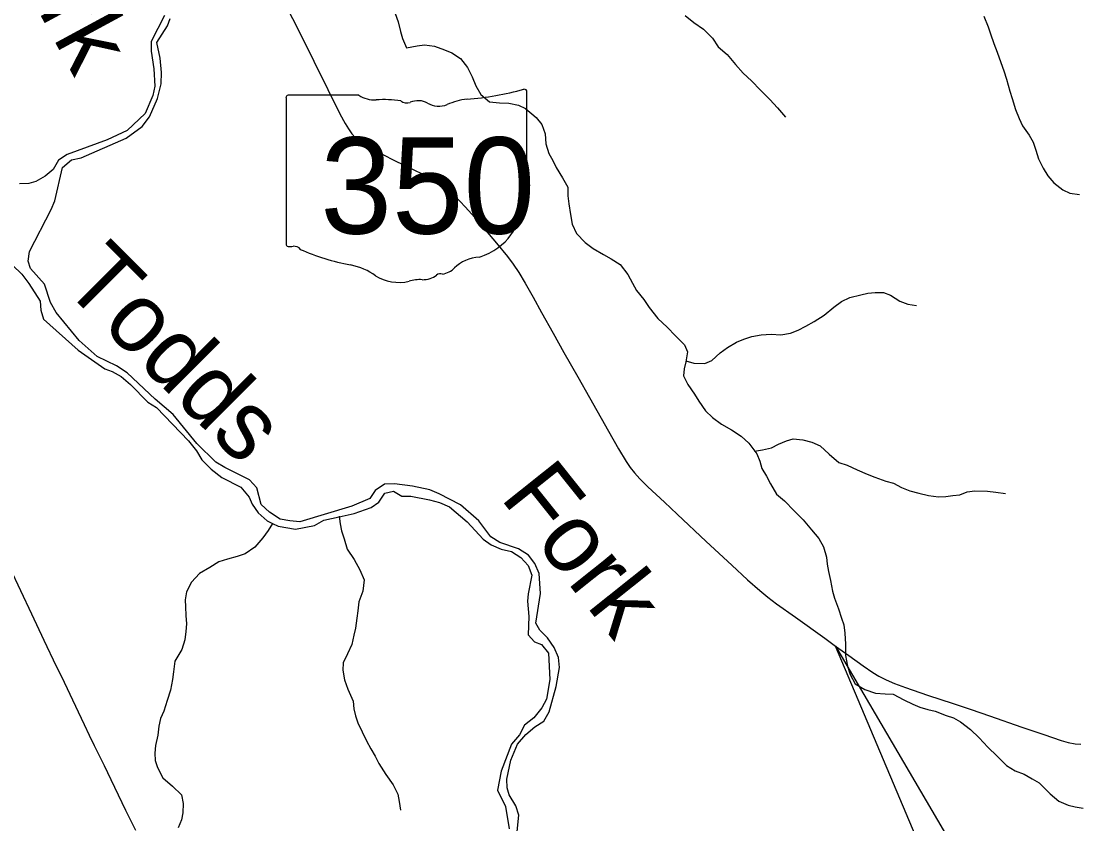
# Model space of a CAD drawing. Extents: x 0 to 34, y 0 to 22.
# Drawn here: x 18.692 to 20.137, y 17.343 to 18.443 of the extents above; entities that cross this region are included whole.
import ezdxf

# ---------------------------------------------------------------- set-up
doc = ezdxf.new("R2010")
doc.units = 0
for name, color, linetype in [('GM_X_County_Road', 7, 'Continuous'), ('GM_X_Major_River', 7, 'Continuous'), ('GM_X_Major_River_Text', 7, 'Continuous'), ('GM_X_Minor_River', 7, 'Continuous'), ('GM_X_State_Location', 7, 'Continuous'), ('GM_X_State_Route', 7, 'Continuous'), ('GM_X_State_Shield', 7, 'Continuous'), ('SH_Text', 7, 'Continuous')]:
    doc.layers.add(name, color=color, linetype=linetype)

msp = doc.modelspace()

# ---------------------------------------------------------------- linework, layer by layer
at = {"layer": 'GM_X_County_Road'}
msp.add_lwpolyline([(18.8488, 17.3345), (18.8352, 17.3618), (18.8252, 17.3825), (18.8151, 17.4038), (18.8059, 17.4227), (18.7996, 17.4354), (18.7922, 17.4504), (18.7855, 17.4644), (18.7784, 17.4788), (18.7701, 17.4962), (18.7474, 17.5445), (18.7402, 17.559), (18.7235, 17.5943), (18.7065, 17.6303), (18.6765, 17.6945)], dxfattribs=at)
at = {"layer": 'GM_X_Major_River'}
for points in [[(18.888, 18.4505), (18.8695, 18.4145), (18.8696, 18.4016), (18.8733, 18.3772), (18.8747, 18.3536), (18.8721, 18.3408), (18.8614, 18.316), (18.8367, 18.2929), (18.8095, 18.2802), (18.7549, 18.26), (18.743, 18.2523), (18.7354, 18.2396), (18.7248, 18.2303), (18.7117, 18.2229), (18.7022, 18.2201), (18.6897, 18.2196)], [(19.3705, 17.3328), (19.3728, 17.3551), (19.3689, 17.3681), (19.3597, 17.383), (19.3569, 17.3926), (19.3564, 17.4047), (19.3622, 17.4308), (19.371, 17.4523), (19.3827, 17.4657), (19.395, 17.4761), (19.4073, 17.4838), (19.4144, 17.4969), (19.4242, 17.5313), (19.4285, 17.5577), (19.4273, 17.5714), (19.4215, 17.5848), (19.4123, 17.5979), (19.4019, 17.6087), (19.396, 17.6183), (19.4025, 17.6588), (19.4008, 17.6861), (19.395, 17.6999), (19.3862, 17.7115), (19.3727, 17.7201), (19.3471, 17.7285), (19.3344, 17.7364), (19.3182, 17.7583), (19.2933, 17.7801), (19.264, 17.7954), (19.2513, 17.8006), (19.2275, 17.8057), (19.2026, 17.8088), (19.1893, 17.8087), (19.1762, 17.7998), (19.1688, 17.789), (19.1443, 17.7785), (19.0731, 17.7571), (19.0594, 17.7581), (19.0462, 17.7607), (19.0317, 17.7701), (19.0201, 17.7805), (19.0145, 17.8034), (19.0042, 17.8146), (18.9704, 17.8312), (18.9584, 17.8387), (18.9321, 17.8642), (18.8999, 17.9039), (18.875, 17.9249), (18.8367, 17.961), (18.8225, 17.9704), (18.7958, 17.9834), (18.7713, 18.0051), (18.7399, 18.0437), (18.7318, 18.0571), (18.7236, 18.0823), (18.7044, 18.104), (18.7012, 18.1139), (18.703, 18.1271), (18.7329, 18.1846), (18.7377, 18.1963), (18.7485, 18.2423), (18.7608, 18.2527), (18.7738, 18.2555), (18.8357, 18.2823), (18.8576, 18.2982), (18.8674, 18.3117), (18.8785, 18.3365), (18.8835, 18.3569), (18.8838, 18.3721), (18.8819, 18.3918), (18.8774, 18.4132), (18.8923, 18.436), (18.8959, 18.4462)], [(18.6668, 18.1214), (18.6925, 18.0959), (18.7024, 18.0835), (18.7179, 18.0593), (18.7187, 18.0468), (18.7223, 18.0346), (18.7699, 17.9919), (18.8061, 17.9665), (18.8163, 17.9629), (18.8286, 17.9558), (18.8413, 17.9449), (18.865, 17.9206), (18.877, 17.9135), (18.9208, 17.8679), (18.9319, 17.8544), (18.9392, 17.8417), (18.9518, 17.8289), (18.9663, 17.8176), (18.9926, 17.8046), (19.0037, 17.7907), (19.008, 17.7812), (19.0161, 17.7692), (19.0284, 17.7584), (19.0356, 17.7547), (19.0434, 17.7509), (19.0672, 17.747), (19.0934, 17.7518), (19.1061, 17.7591), (19.127, 17.7639), (19.1476, 17.7685), (19.1708, 17.7764), (19.1812, 17.7838), (19.1894, 17.7962), (19.2016, 17.799), (19.2128, 17.7923), (19.2249, 17.792), (19.2506, 17.787), (19.2645, 17.7833), (19.2781, 17.7777), (19.3023, 17.7571), (19.3241, 17.7332), (19.335, 17.7254), (19.3488, 17.7194), (19.3628, 17.7165), (19.3755, 17.7079), (19.3855, 17.6971), (19.3906, 17.6841), (19.3855, 17.6584), (19.3849, 17.6485), (19.3867, 17.6272), (19.3855, 17.6022), (19.3944, 17.5925), (19.4041, 17.5889), (19.4137, 17.577), (19.4153, 17.5409), (19.4106, 17.5141), (19.4046, 17.5024), (19.3934, 17.4886), (19.3807, 17.4786), (19.3739, 17.4651), (19.3631, 17.4524), (19.3487, 17.4155), (19.3436, 17.3894), (19.3545, 17.3672), (19.3599, 17.3364)]]:
    msp.add_lwpolyline(points, dxfattribs=at)
at = {"layer": 'GM_X_Minor_River'}
for points in [[(19.2037, 18.453), (19.2076, 18.4415), (19.2111, 18.4286), (19.2136, 18.4187), (19.2194, 18.406), (19.2338, 18.4088), (19.2437, 18.4101), (19.2573, 18.4083), (19.2712, 18.4035), (19.2814, 18.3991), (19.2933, 18.3913), (19.3029, 18.3793), (19.3091, 18.3663), (19.3141, 18.3541), (19.3207, 18.3422), (19.3326, 18.3321), (19.3466, 18.3307), (19.3591, 18.3304), (19.3723, 18.3275), (19.3821, 18.3231), (19.3966, 18.3107), (19.4044, 18.3011), (19.409, 18.2881), (19.4099, 18.2744), (19.4142, 18.2614), (19.4196, 18.2518), (19.424, 18.2422), (19.4328, 18.228), (19.4401, 18.2154), (19.4402, 18.2032), (19.4415, 18.1926), (19.4435, 18.1777), (19.4459, 18.1644), (19.4517, 18.1518), (19.4635, 18.1394), (19.4747, 18.1312), (19.489, 18.123), (19.4991, 18.1171), (19.5118, 18.1092), (19.5221, 18.0958)], [(19.6006, 18.4505), (19.6126, 18.4407), (19.6256, 18.4317), (19.6379, 18.4194), (19.6456, 18.4075), (19.6579, 18.397), (19.6693, 18.3831), (19.6801, 18.3715), (19.6912, 18.361), (19.7035, 18.3479), (19.7165, 18.3351), (19.7268, 18.3239), (19.7379, 18.3112)], [(20.0094, 18.4496), (20.0151, 18.4347), (20.0187, 18.4251), (20.023, 18.4118), (20.0277, 18.3999), (20.0327, 18.3861), (20.0366, 18.3747)], [(20.0366, 18.3747), (20.0402, 18.3632), (20.0448, 18.3465), (20.048, 18.3365), (20.0526, 18.3216), (20.0577, 18.3094), (20.0624, 18.2994), (20.0716, 18.2864), (20.0771, 18.2768), (20.0806, 18.2661), (20.0842, 18.2539), (20.0907, 18.2412), (20.097, 18.2308), (20.1051, 18.2212), (20.1174, 18.2115), (20.1272, 18.2071), (20.1404, 18.205)], [(19.5221, 18.0958), (19.5287, 18.0839), (19.5338, 18.0739), (19.5438, 18.0612), (19.5511, 18.0504), (19.5633, 18.0354), (19.576, 18.0234), (19.5875, 18.0118), (19.5997, 17.9994), (19.6037, 17.9898), (19.6015, 17.9762), (19.599, 17.9664), (19.5985, 17.9569), (19.6043, 17.945), (19.6135, 17.9319), (19.6193, 17.922), (19.6282, 17.9089), (19.6378, 17.9), (19.6505, 17.8906), (19.664, 17.8828), (19.6771, 17.8742), (19.6875, 17.8649), (19.6986, 17.8502), (19.7029, 17.8399), (19.7057, 17.83), (19.7119, 17.8196), (19.7174, 17.8092), (19.7258, 17.795), (19.7366, 17.7857), (19.7496, 17.7722), (19.7622, 17.7598), (19.7733, 17.7459), (19.7833, 17.7343), (19.7899, 17.7228), (19.7942, 17.7087), (19.7951, 17.6992), (19.7968, 17.6889), (19.7996, 17.6767), (19.8023, 17.6619), (19.8051, 17.6523), (19.8105, 17.6378), (19.8144, 17.6252), (19.8176, 17.6157), (19.8189, 17.6046), (19.8201, 17.5894), (19.8202, 17.5739), (19.8229, 17.5594), (19.8265, 17.548), (19.8334, 17.5349), (19.8465, 17.5275), (19.8612, 17.5222), (19.8744, 17.5216), (19.8854, 17.521), (19.9, 17.5131), (19.912, 17.5072), (19.9218, 17.5032), (19.9327, 17.5), (19.9429, 17.4975), (19.9579, 17.4919), (19.9677, 17.4886), (19.9774, 17.4831), (19.9909, 17.4726), (20.0031, 17.461), (20.015, 17.4486), (20.0276, 17.4359), (20.0402, 17.4235), (20.0522, 17.416), (20.0646, 17.4112), (20.0755, 17.4049), (20.0852, 17.3994), (20.1, 17.3847), (20.112, 17.3746), (20.1247, 17.3691), (20.1345, 17.3666), (20.1455, 17.3649)], [(19.6017, 17.9774), (19.6125, 17.9741), (19.6276, 17.9738), (19.6372, 17.9778), (19.6484, 17.9885), (19.6587, 17.9956), (19.671, 18.0029), (19.6809, 18.0073), (19.6916, 18.0108), (19.7046, 18.0132), (19.7182, 18.0141), (19.7315, 18.0131), (19.7448, 18.0151), (19.7554, 18.0194), (19.7658, 18.0249), (19.7773, 18.0311), (19.7907, 18.04), (19.8042, 18.0511), (19.8146, 18.0585), (19.8261, 18.064), (19.8409, 18.0678), (19.8504, 18.0703), (19.8607, 18.0712), (19.8721, 18.071), (19.8818, 18.0674), (19.8942, 18.0592), (19.9054, 18.0552), (19.9172, 18.0534)], [(19.6957, 17.8539), (19.7062, 17.8554), (19.7188, 17.8585), (19.7284, 17.8633), (19.7391, 17.868), (19.7486, 17.8705), (19.7618, 17.8691), (19.7739, 17.8662), (19.7852, 17.861), (19.7978, 17.8494), (19.8108, 17.8381), (19.8225, 17.8345), (19.836, 17.8281), (19.8495, 17.8222), (19.86, 17.8182), (19.8751, 17.8126), (19.8856, 17.8097), (19.8965, 17.8038), (19.9082, 17.7994), (19.9202, 17.7961), (19.9334, 17.7932), (19.9474, 17.7914), (19.9572, 17.7916), (19.9667, 17.7929), (19.9766, 17.7939), (19.9865, 17.7979), (19.9972, 17.7995), (20.0142, 17.7988), (20.0259, 17.7975), (20.0388, 17.7957)], [(19.1269, 17.7645), (19.1283, 17.7541), (19.1304, 17.7446), (19.134, 17.7339), (19.1382, 17.7194), (19.1474, 17.7056), (19.1554, 17.6914), (19.1612, 17.6776), (19.1594, 17.6621), (19.1538, 17.6474), (19.1528, 17.6349), (19.1514, 17.625), (19.1493, 17.6114), (19.1472, 17.6016), (19.1442, 17.5888), (19.1383, 17.5764), (19.1324, 17.564), (19.1322, 17.5537), (19.1342, 17.5408), (19.1388, 17.5278), (19.1461, 17.5113), (19.147, 17.5011), (19.1494, 17.4912), (19.1526, 17.4816), (19.1643, 17.4571), (19.1705, 17.446), (19.1763, 17.436), (19.1811, 17.426), (19.191, 17.411), (19.2009, 17.3968), (19.2071, 17.3842), (19.2092, 17.3739), (19.2108, 17.3621)], [(19.0356, 17.7547), (19.03, 17.7451), (19.0226, 17.735), (19.0117, 17.7223), (18.9983, 17.7131), (18.9876, 17.7095), (18.9743, 17.706), (18.9624, 17.702), (18.9498, 17.6943), (18.936, 17.6862), (18.9248, 17.6743), (18.918, 17.6612), (18.9163, 17.6502), (18.9165, 17.6407), (18.917, 17.6289), (18.9179, 17.6171), (18.9173, 17.6069), (18.9159, 17.5952), (18.9115, 17.582), (18.9021, 17.5662), (18.9003, 17.5515), (18.8989, 17.5409), (18.8963, 17.5265), (18.8915, 17.5122), (18.887, 17.4979), (18.8827, 17.4877), (18.8802, 17.4771), (18.8788, 17.4646), (18.8755, 17.4507), (18.8749, 17.4404), (18.8754, 17.4302), (18.8782, 17.4206), (18.8859, 17.4065), (18.8989, 17.3948), (18.9112, 17.3832), (18.9136, 17.3714), (18.913, 17.3585), (18.9112, 17.3487), (18.9069, 17.3381)]]:
    msp.add_lwpolyline(points, dxfattribs=at)
at = {"layer": 'GM_X_State_Route'}
msp.add_lwpolyline([(19.0531, 18.4657), (19.0733, 18.4266), (19.1115, 18.3492), (19.1281, 18.3158), (19.1351, 18.3026), (19.1397, 18.2951), (19.1445, 18.2885), (19.1495, 18.2829), (19.1545, 18.2781), (19.1589, 18.2746), (19.1632, 18.2719), (19.1703, 18.268), (19.1859, 18.2602), (19.2038, 18.2515), (19.2239, 18.2418), (19.2461, 18.2307), (19.2553, 18.2256), (19.2648, 18.2199), (19.2714, 18.2153), (19.2786, 18.2094), (19.2857, 18.2027), (19.2994, 18.1883), (19.3087, 18.1783), (19.3152, 18.1708), (19.3423, 18.1384), (19.3573, 18.1202), (19.3652, 18.1099), (19.3728, 18.0986), (19.3818, 18.0837), (19.3924, 18.0648), (19.404, 18.0436), (19.4197, 18.0153), (19.4347, 17.9888), (19.4538, 17.9553), (19.4695, 17.9271), (19.4956, 17.8812), (19.5094, 17.8569), (19.5197, 17.8398), (19.5253, 17.8315), (19.5311, 17.8242), (19.5386, 17.8159), (19.5497, 17.8049), (19.5724, 17.7837), (19.5897, 17.7676), (19.6295, 17.7302), (19.6645, 17.6975), (19.6859, 17.6776), (19.7027, 17.6628), (19.7138, 17.6537), (19.7257, 17.6448), (19.7515, 17.6264), (19.7918, 17.5975), (19.8064, 17.5869), (19.8244, 17.5738), (19.8441, 17.5596), (19.8575, 17.5506), (19.8656, 17.5458), (19.8756, 17.5407), (19.887, 17.5356), (19.9022, 17.53), (19.9322, 17.5198), (19.9676, 17.5082), (19.9905, 17.5003), (20.0052, 17.4953), (20.0169, 17.4912), (20.0615, 17.4758), (20.0914, 17.4656), (20.115, 17.4577), (20.1246, 17.4549), (20.1345, 17.4531), (20.142, 17.4523)], dxfattribs=at)
at = {"layer": 'GM_X_State_Shield'}
for p, q in [((19.0543, 18.3376), (19.0543, 18.1374)), ((19.154, 18.341), (19.0575, 18.341)), ((19.3838, 18.2413), (19.3838, 18.346)), ((19.3838, 18.2413), (19.3838, 18.2413))]:
    msp.add_line(p, q, dxfattribs=at)
for centre, major_axis, start_param, end_param in [((19.058, 18.338), (0.00382, 0), 1.712693, 3.28349), ((19.177, 18.3642), (0.037, 0), 4.042523, 4.731795), ((19.2664, 18.6138), (0.3495, 0), 4.814394, 5.042369), ((19.3802, 18.3464), (0.00367, 0), 6.141152, 7.989035), ((19.1893, 18.2287), (0.133, 0), 1.404758, 1.657858), ((19.2195, 18.339), (0.0107, 0), 3.836095, 5.185415), ((19.2352, 18.3159), (0.0222, 0), 0.950623, 2.079405), ((19.2638, 18.3476), (0.0267, 0), 4.081561, 5.145723), ((19.311, 18.2799), (0.0703, 0), 1.699011, 2.107814), ((19.383, 18.2336), (0.00568, 0), 1.883978, 3.671073), ((19.3799, 18.2409), (0.00393, 0), 5.05454, 6.418171), ((19.3469, 18.2204), (0.0341, 0), 5.934695, 6.695948), ((19.397, 18.1975), (0.0248, 0), 2.387724, 3.262537), ((19.286, 18.1842), (0.0874, 0), 5.101752, 6.440018), ((19.0581, 18.137), (0.00385, 0), 3.00124, 4.508301), ((19.0647, 18.1259), (0.0106, 0), 0.519207, 1.627899), ((19.0587, 18.1575), (0.0294, 0), 4.665946, 4.897461), ((19.1985, 18.3057), (0.2524, 0), 4.195997, 4.488961), ((19.1232, 18.0475), (0.079, 0), 0.823519, 1.323587), ((19.3229, 18.0813), (0.0479, 0), 1.647645, 2.488434), ((19.2087, 18.1249), (0.0501, 0), 4.026481, 4.996735), ((19.2413, 18.1099), (0.0267, 0), 4.691044, 5.507374), ((19.2654, 18.0905), (0.00752, 0), 1.147584, 2.315152), ((19.2622, 18.1181), (0.0282, 0), 4.937069, 5.64225), ((19.2376, 18.0557), (0.0412, 0), 1.495662, 1.94098)]:
    msp.add_ellipse(centre, major_axis=major_axis, ratio=0.8, start_param=start_param, end_param=end_param, dxfattribs=at)
at = {"layer": 'SH_Text'}
msp.add_lwpolyline([(20.1277, 17.0385), (20.1277, 16.8259), (19.8064, 17.5869)], close=True, dxfattribs=at)

# ---------------------------------------------------------------- texts
at = {"layer": 'GM_X_Major_River_Text'}
for s, rotation, p in [('Fork', 298.4456, (18.6441, 18.5873)), ('Todds', 315.032, (18.7454, 18.0805)), ('Fork', 308.5704, (19.346, 17.7904))]:
    msp.add_text(s, height=0.09469, rotation=rotation, dxfattribs=at).set_placement(p)
at = {"layer": 'GM_X_State_Location'}
for s, p in [('s', (19.2154, 18.2242)), ('r', (19.2153, 18.2242))]:
    msp.add_text(s, height=0.000189, dxfattribs=at).set_placement(p)
msp.add_text('350', height=0.000189, rotation=0, dxfattribs=at).set_placement((19.1485, 18.2104))
at = {"layer": 'GM_X_State_Shield'}
msp.add_text('350', height=0.13184, dxfattribs=at).set_placement((19.1012, 18.1516))

doc.saveas('drawing.dxf')
